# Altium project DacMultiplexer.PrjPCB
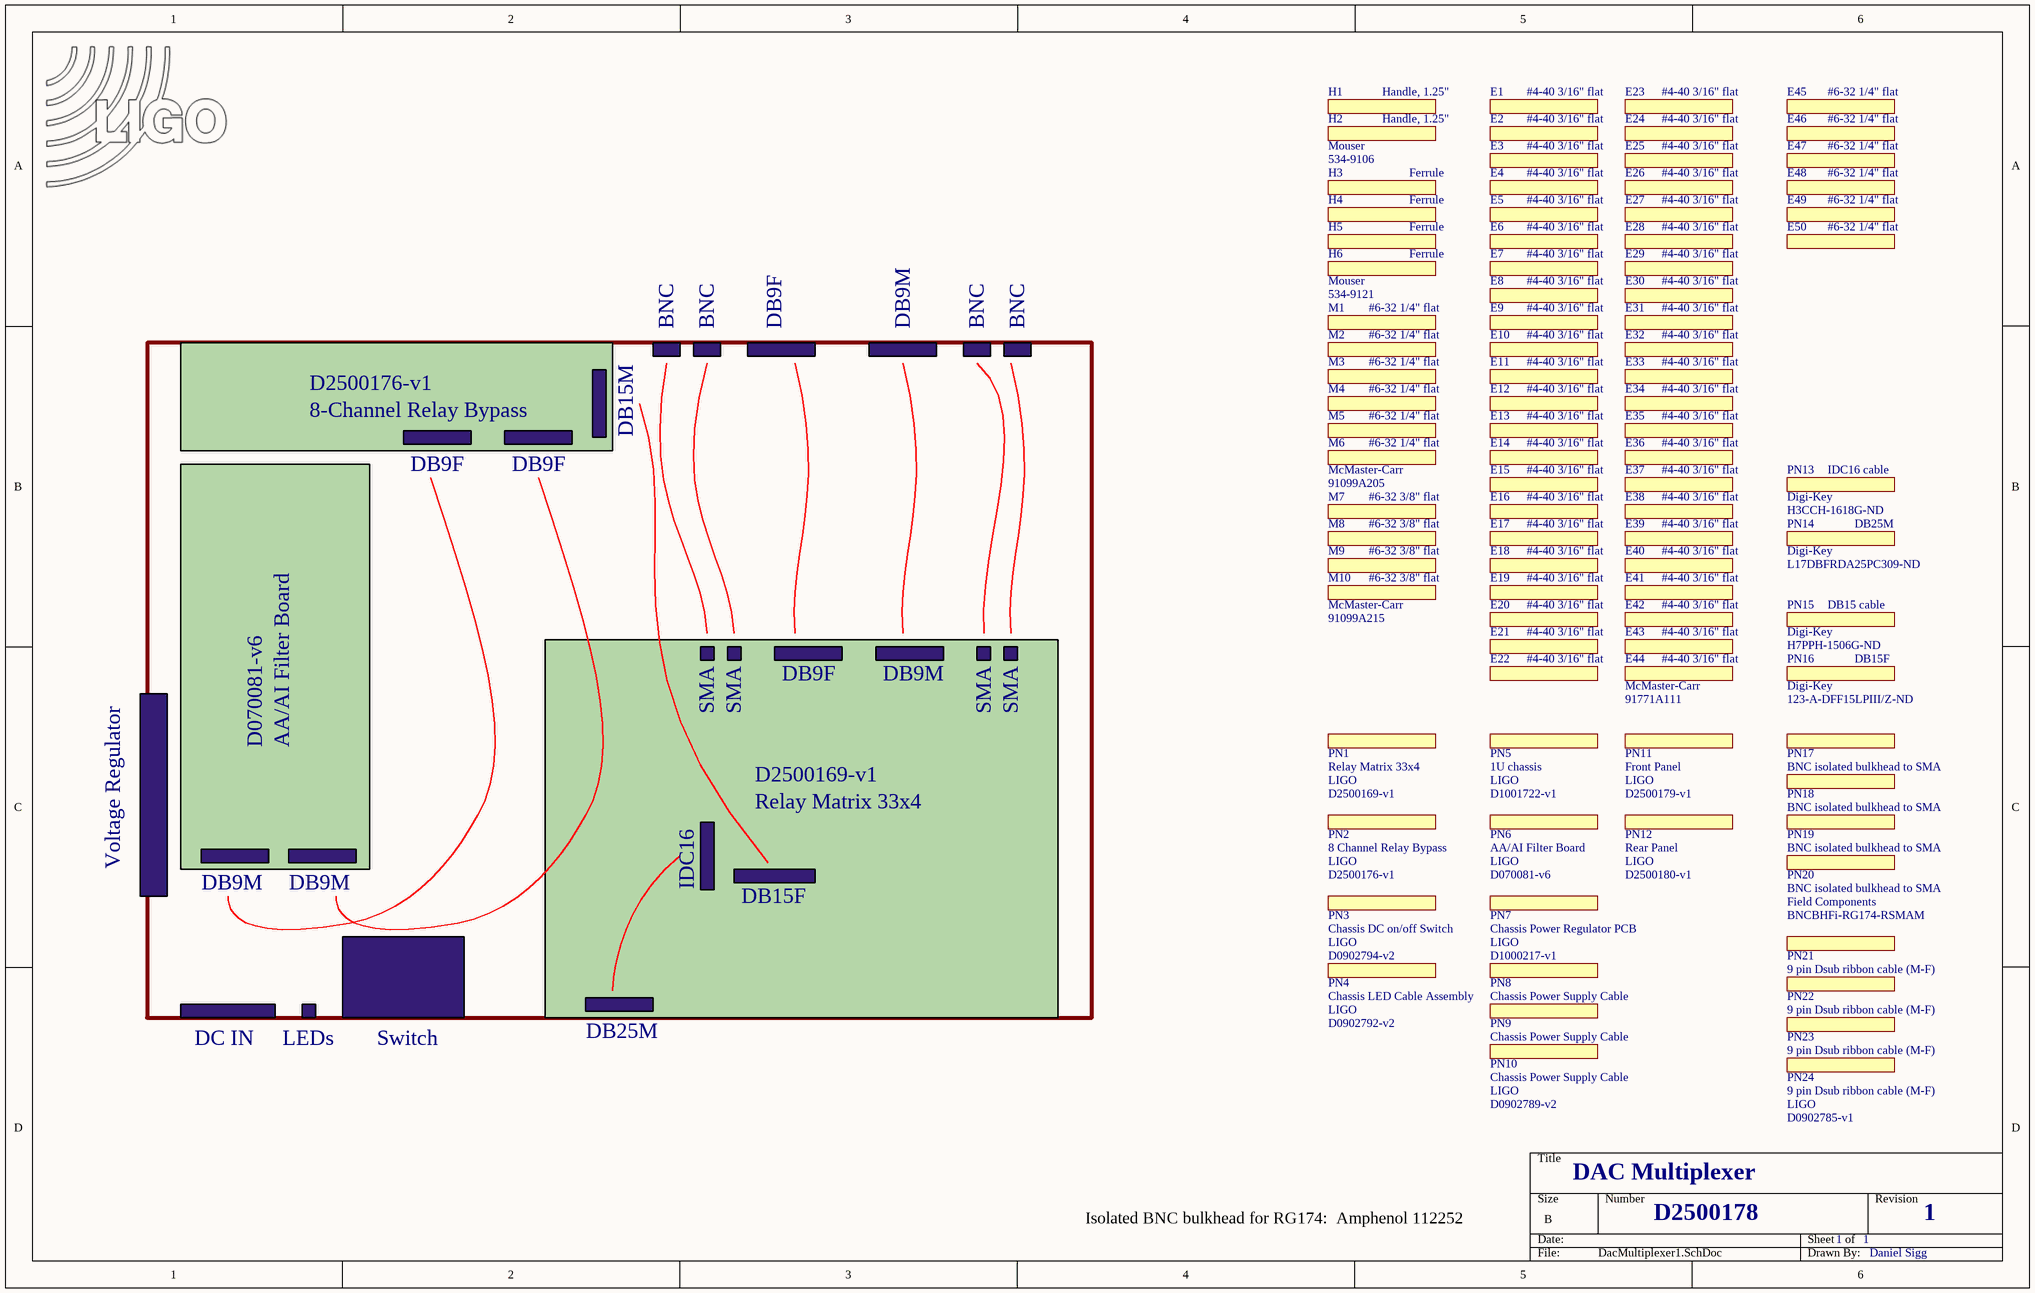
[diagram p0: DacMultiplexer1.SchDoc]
DCC: D2500178; REV: 1
1 sheet, 91 parts. Net scope: global (net labels, ports and power ports of the same name join across sheets).

## Sheet DacMultiplexer1.SchDoc: DAC Multiplexer
size B; Engineer: Daniel Sigg; DocumentNumber: D2500178; Revision: 1; SheetNumber: 1; SheetTotal: 1; PageSetup: Record=PageOptions¦CenterHorizontal=True¦CenterVertical=True¦PrintScale=1.12¦XCorrection=1.00¦YCorrection=1.00¦PrintKind=0¦BorderSize=5000000¦LeftOffset=0¦BottomOffset=0¦Orientation=2¦PaperLength=1000¦PaperWidth=1000¦Scale=100¦PaperSource=7¦PrintQuality=-4¦MediaType=1¦DitherType=10¦PaperKind=11 x 17¦PrintScaleMode=1

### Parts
E1  #4-40 3/16" flat  (mechanical)
E2  #4-40 3/16" flat  (mechanical)
E3  #4-40 3/16" flat  (mechanical)
E4  #4-40 3/16" flat  (mechanical)
E5  #4-40 3/16" flat  (mechanical)
E6  #4-40 3/16" flat  (mechanical)
E7  #4-40 3/16" flat  (mechanical)
E8  #4-40 3/16" flat  (mechanical)
E9  #4-40 3/16" flat  (mechanical)
E10  #4-40 3/16" flat  (mechanical)
E11  #4-40 3/16" flat  (mechanical)
E12  #4-40 3/16" flat  (mechanical)
E13  #4-40 3/16" flat  (mechanical)
E14  #4-40 3/16" flat  (mechanical)
E15  #4-40 3/16" flat  (mechanical)
E16  #4-40 3/16" flat  (mechanical)
E17  #4-40 3/16" flat  (mechanical)
E18  #4-40 3/16" flat  (mechanical)
E19  #4-40 3/16" flat  (mechanical)
E20  #4-40 3/16" flat  (mechanical)
E21  #4-40 3/16" flat  (mechanical)
E22  #4-40 3/16" flat  (mechanical)
E23  #4-40 3/16" flat  (mechanical)
E24  #4-40 3/16" flat  (mechanical)
E25  #4-40 3/16" flat  (mechanical)
E26  #4-40 3/16" flat  (mechanical)
E27  #4-40 3/16" flat  (mechanical)
E28  #4-40 3/16" flat  (mechanical)
E29  #4-40 3/16" flat  (mechanical)
E30  #4-40 3/16" flat  (mechanical)
E31  #4-40 3/16" flat  (mechanical)
E32  #4-40 3/16" flat  (mechanical)
E33  #4-40 3/16" flat  (mechanical)
E34  #4-40 3/16" flat  (mechanical)
E35  #4-40 3/16" flat  (mechanical)
E36  #4-40 3/16" flat  (mechanical)
E37  #4-40 3/16" flat  (mechanical)
E38  #4-40 3/16" flat  (mechanical)
E39  #4-40 3/16" flat  (mechanical)
E40  #4-40 3/16" flat  (mechanical)
E41  #4-40 3/16" flat  (mechanical)
E42  #4-40 3/16" flat  (mechanical)
E43  #4-40 3/16" flat  (mechanical)
E44  #4-40 3/16" flat  Part Number: 91771A111  Distributor: McMaster-Carr  (mechanical)
E45  #6-32 1/4" flat  (mechanical)
E46  #6-32 1/4" flat  (mechanical)
E47  #6-32 1/4" flat  (mechanical)
E48  #6-32 1/4" flat  (mechanical)
E49  #6-32 1/4" flat  (mechanical)
E50  #6-32 1/4" flat  (mechanical)
H1  Handle, 1.25"  (mechanical)
H2  Handle, 1.25"  Part Number: 534-9106  Distributor: Mouser  (mechanical)
H3  Ferrule  (mechanical)
H4  Ferrule  (mechanical)
H5  Ferrule  (mechanical)
H6  Ferrule  Part Number: 534-9121  Distributor: Mouser  (mechanical)
LOGO1  LIGO logo  [LIGO_LOGO]  (value not drawn)  (no BOM)
M1  #6-32 1/4" flat  (mechanical)
M2  #6-32 1/4" flat  (mechanical)
M3  #6-32 1/4" flat  (mechanical)
M4  #6-32 1/4" flat  (mechanical)
M5  #6-32 1/4" flat  (mechanical)
M6  #6-32 1/4" flat  Part Number: 91099A205  Distributor: McMaster-Carr  (mechanical)
M7  #6-32 3/8" flat  (mechanical)
M8  #6-32 3/8" flat  (mechanical)
M9  #6-32 3/8" flat  (mechanical)
M10  #6-32 3/8" flat  Part Number: 91099A215  Distributor: McMaster-Carr  (mechanical)
PN1  Relay Matrix 33x4  Part Number: D2500169-v1  Distributor: LIGO  (mechanical)
PN2  8 Channel Relay Bypass  Part Number: D2500176-v1  Distributor: LIGO  (mechanical)
PN3  Chassis DC on/off Switch  Part Number: D0902794-v2  Distributor: LIGO  (mechanical)
PN4  Chassis LED Cable Assembly  Part Number: D0902792-v2  Distributor: LIGO  (mechanical)
PN5  1U chassis  Part Number: D1001722-v1  Distributor: LIGO  (mechanical)
PN6  AA/AI Filter Board  Part Number: D070081-v6  Distributor: LIGO  (mechanical)
PN7  Chassis Power Regulator PCB  Part Number: D1000217-v1  Distributor: LIGO  (mechanical)
PN8  Chassis Power Supply Cable  (mechanical)
PN9  Chassis Power Supply Cable  (mechanical)
PN10  Chassis Power Supply Cable  Part Number: D0902789-v2  Distributor: LIGO  (mechanical)
PN11  Front Panel  Part Number: D2500179-v1  Distributor: LIGO  (mechanical)
PN12  Rear Panel  Part Number: D2500180-v1  Distributor: LIGO  (mechanical)
PN13  IDC16 cable  Part Number: H3CCH-1618G-ND  Distributor: Digi-Key  (mechanical)
PN14  DB25M  Part Number: L17DBFRDA25PC309-ND  Distributor: Digi-Key  (mechanical)
PN15  DB15 cable  Part Number: H7PPH-1506G-ND  Distributor: Digi-Key  (mechanical)
PN16  DB15F  Part Number: 123-A-DFF15LPIII/Z-ND  Distributor: Digi-Key  (mechanical)
PN17  BNC isolated bulkhead to SMA  (mechanical)
PN18  BNC isolated bulkhead to SMA  (mechanical)
PN19  BNC isolated bulkhead to SMA  (mechanical)
PN20  BNC isolated bulkhead to SMA  Part Number: BNCBHFi-RG174-RSMAM  Distributor: Field Components  (mechanical)
PN21  9 pin Dsub ribbon cable (M-F)  (mechanical)
PN22  9 pin Dsub ribbon cable (M-F)  (mechanical)
PN23  9 pin Dsub ribbon cable (M-F)  (mechanical)
PN24  9 pin Dsub ribbon cable (M-F)  Part Number: D0902785-v1  Distributor: LIGO  (mechanical)

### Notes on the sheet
- BNC
- DB9F
- DB9M
- 8-Channel Relay Bypass
- D2500176-v1
- DB15M
- D070081-v6
- AA/AI Filter Board
- SMA
- Relay Matrix 33x4
- D2500169-v1
- Voltage Regulator
- IDC16
- DB15F
- DC IN
- LEDs
- Switch
- DB25M
- DAC Multiplexer
- Isolated BNC bulkhead for RG174:  Amphenol 112252
- 1
- Daniel Sigg

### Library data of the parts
E1-E43 = Partlist: #4-40 3/16" flat head screw; Part Number: 91771A111
E44 = Partlist: #4-40 3/16" flat head screw
E45-E50 M1-M5 = Partlist: #6-32 1/4" flat head screw; Part Number: 91099A205
H1 = Partlist: Rack handle; Part Number: 534-9106
H2 = Partlist: Rack handle
H3-H5 = Partlist: Part Number: 534-9121
H6 = Partlist
LOGO1 = LIGO_logo
M6 = Partlist: #6-32 1/4" flat head screw
M7-M9 = Partlist: #6-32 3/8" flat head screw; Part Number: 91099A215
M10 PN13-PN16 = Partlist: #6-32 3/8" flat head screw
PN1 PN2 PN6 = Partlist: PCB
PN3-PN5 PN7 PN10 PN20 PN24 = Partlist: chassis
PN8 PN9 = Partlist: chassis; Part Number: D0902789-v2
PN11 PN12 = Partlist: panel
PN17-PN19 = Partlist: chassis; Part Number: BNCBHFi-RG174-RSMAM
PN21-PN23 = Partlist: chassis; Part Number: D0902785-v1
